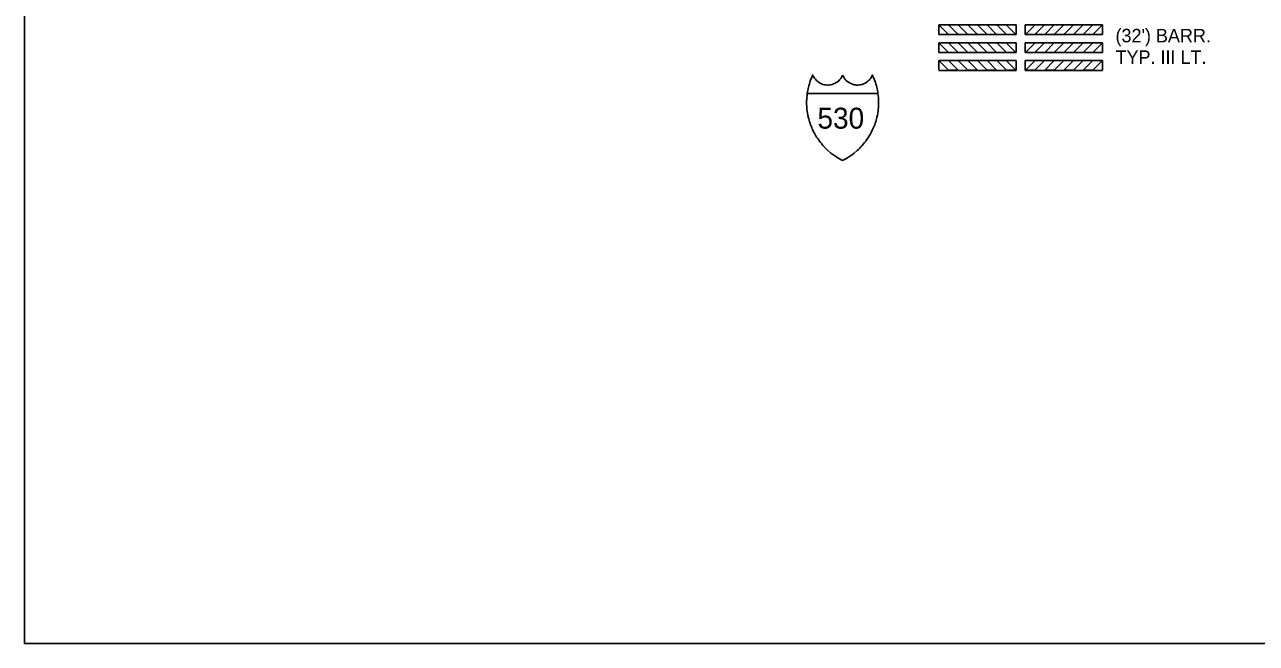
# Model space of a CAD drawing. Extents: x 754662 to 914198, y 935180 to 1039412.
# Drawn here: x 754662 to 837096, y 935180 to 976576 of the extents above; entities that cross this region are included whole.
import ezdxf

# ---------------------------------------------------------------- set-up
doc = ezdxf.new("R2010")
doc.units = 0
for name, color, linetype in [('G-ANNO-TEXT', 7, 'Continuous'), ('G-No Plot-Anchor', 7, 'Continuous'), ('Level 14', 7, 'Continuous'), ('Level 61', 7, 'Continuous'), ('Level 62', 7, 'Continuous')]:
    doc.layers.add(name, color=color, linetype=linetype)

msp = doc.modelspace()

# ---------------------------------------------------------------- linework, layer by layer
at = {"layer": 'G-No Plot-Anchor'}
msp.add_lwpolyline([(870863, 1039412), (884363, 1039412), (884363, 1034457), (914198, 1034457), (914198, 935180), (754662, 935180), (754662, 1039412)], close=True, dxfattribs=at)
at = {"layer": 'Level 14'}
for points in [[(807040, 971965), (807058, 972078), (807075, 972178), (807102, 972307), (807121, 972391), (807147, 972491), (807180, 972608), (807210, 972706), (807244, 972807), (807289, 972931), (807335, 973048), (807374, 973138), (807406, 973210), (807441, 973133), (807481, 973059), (807525, 972992), (807583, 972918), (807628, 972868), (807685, 972813), (807742, 972765), (807803, 972720), (807901, 972662), (808002, 972615), (808093, 972582), (808183, 972559), (808280, 972543), (808392, 972536), (808466, 972537), (808551, 972545), (808626, 972558), (808707, 972578), (808788, 972605), (808898, 972653), (808973, 972695), (809061, 972755), (809145, 972826), (809207, 972888), (809277, 972973), (809335, 973060), (809369, 973121), (809406, 973201)], [(809406, 973201), (809443, 973121), (809477, 973060), (809535, 972973), (809605, 972888), (809666, 972826), (809751, 972755), (809838, 972695), (809914, 972653), (810023, 972605), (810105, 972578), (810185, 972558), (810261, 972545), (810346, 972537), (810419, 972536), (810532, 972543), (810628, 972559), (810718, 972582), (810809, 972615), (810910, 972662), (811008, 972720), (811070, 972765), (811127, 972813), (811183, 972868), (811229, 972918), (811286, 972992), (811330, 973059), (811371, 973133), (811406, 973210), (811438, 973138), (811476, 973048), (811523, 972931), (811568, 972807), (811602, 972706), (811632, 972608), (811665, 972491), (811690, 972391), (811710, 972307), (811736, 972178), (811754, 972078), (811771, 971965)], [(809406, 967484), (809199, 967594), (809016, 967704), (808816, 967840), (808628, 967981), (808424, 968156), (808347, 968227), (808260, 968312), (808180, 968395), (808092, 968492), (808005, 968592), (807933, 968681), (807855, 968783), (807783, 968882), (807722, 968972), (807668, 969056), (807623, 969128), (807564, 969229), (807518, 969312), (807467, 969408), (807418, 969508), (807375, 969601), (807336, 969690), (807295, 969790), (807260, 969883), (807226, 969980), (807193, 970081), (807162, 970185), (807134, 970284), (807111, 970378), (807092, 970462), (807079, 970524), (807056, 970644), (807035, 970784), (807020, 970899), (807009, 971021), (807003, 971120), (806999, 971246), (806997, 971363), (807000, 971493), (807003, 971578), (807008, 971657), (807012, 971706), (807024, 971834), (807040, 971965)], [(811771, 971965), (807040, 971965)], [(807040, 971965), (811771, 971965)], [(811771, 971965), (811788, 971834), (811800, 971706), (811804, 971657), (811808, 971578), (811812, 971493), (811814, 971363), (811813, 971246), (811808, 971120), (811802, 971021), (811792, 970899), (811777, 970784), (811755, 970644), (811733, 970524), (811720, 970462), (811701, 970378), (811677, 970284), (811650, 970185), (811619, 970081), (811586, 969980), (811552, 969883), (811516, 969790), (811475, 969690), (811437, 969601), (811394, 969508), (811345, 969408), (811294, 969312), (811248, 969229), (811189, 969128), (811144, 969056), (811090, 968972), (811028, 968882), (810957, 968783), (810879, 968681), (810807, 968592), (810720, 968492), (810632, 968395), (810551, 968312), (810465, 968227), (810388, 968156), (810183, 967981), (809996, 967840), (809795, 967704), (809613, 967594), (809406, 967484)]]:
    msp.add_lwpolyline(points, dxfattribs=at)
at = {"layer": 'Level 61'}
for p, q in [((821017, 976570), (815854, 976570)), ((815854, 975922), (815854, 976570)), ((821017, 975924), (821017, 976570)), ((821627, 975924), (821627, 976570)), ((821627, 976570), (826790, 976570)), ((826790, 975922), (826790, 976570)), ((821017, 975910), (815854, 975910)), ((821017, 975368), (815854, 975368)), ((815854, 974722), (815854, 975368)), ((821017, 974722), (821017, 975368)), ((821627, 975910), (826790, 975910)), ((821627, 975368), (826790, 975368)), ((821627, 974722), (821627, 975368)), ((826790, 974722), (826790, 975368)), ((821017, 974722), (815854, 974722)), ((821627, 974722), (826790, 974722)), ((815854, 973524), (815854, 974171)), ((821017, 974171), (815854, 974171)), ((821017, 973524), (821017, 974171)), ((821627, 974171), (826790, 974171)), ((821627, 973524), (821627, 974171)), ((826790, 973524), (826790, 974171)), ((821017, 973511), (815854, 973511)), ((821627, 973511), (826790, 973511))]:
    msp.add_line(p, q, dxfattribs=at)
for points in [[(815854, 976570), (816489, 976568), (817133, 975924), (816501, 975924)], [(817144, 976570), (817779, 976568), (818423, 975924), (817791, 975924)], [(818434, 976570), (819069, 976568), (819713, 975924), (819081, 975924)], [(819724, 976570), (820359, 976568), (821003, 975924), (820371, 975924)], [(822920, 976570), (822285, 976568), (821641, 975924), (822274, 975924)], [(824210, 976570), (823575, 976568), (822931, 975924), (823564, 975924)], [(825500, 976570), (824865, 976568), (824221, 975924), (824854, 975924)], [(826790, 976570), (826155, 976568), (825511, 975924), (826144, 975924)], [(815854, 975368), (816489, 975367), (817133, 974722), (816501, 974722)], [(817144, 975368), (817779, 975367), (818423, 974722), (817791, 974722)], [(818434, 975368), (819069, 975367), (819713, 974722), (819081, 974722)], [(819724, 975368), (820359, 975367), (821003, 974722), (820371, 974722)], [(822920, 975368), (822285, 975367), (821641, 974722), (822274, 974722)], [(824210, 975368), (823575, 975367), (822931, 974722), (823564, 974722)], [(825500, 975368), (824865, 975367), (824221, 974722), (824854, 974722)], [(826790, 975368), (826155, 975367), (825511, 974722), (826144, 974722)], [(815854, 974171), (816489, 974169), (817133, 973524), (816501, 973524)], [(817144, 974171), (817779, 974169), (818423, 973524), (817791, 973524)], [(818434, 974171), (819069, 974169), (819713, 973524), (819081, 973524)], [(819724, 974171), (820359, 974169), (821003, 973524), (820371, 973524)], [(822920, 974171), (822285, 974169), (821641, 973524), (822274, 973524)], [(824210, 974171), (823575, 974169), (822931, 973524), (823564, 973524)], [(825500, 974171), (824865, 974169), (824221, 973524), (824854, 973524)], [(826790, 974171), (826155, 974169), (825511, 973524), (826144, 973524)]]:
    msp.add_lwpolyline(points, close=True, dxfattribs=at)

# ---------------------------------------------------------------- texts
at = {"layer": 'G-ANNO-TEXT'}
msp.add_text('530', height=1402.1, dxfattribs=at).set_placement((807721, 969617))
at = {"layer": 'Level 62'}
for s, p in [("(32') BARR.", (827670, 975394)), ('TYP. III LT.', (827670, 973953))]:
    msp.add_text(s, height=900.31, dxfattribs=at).set_placement(p)

doc.saveas('drawing.dxf')
